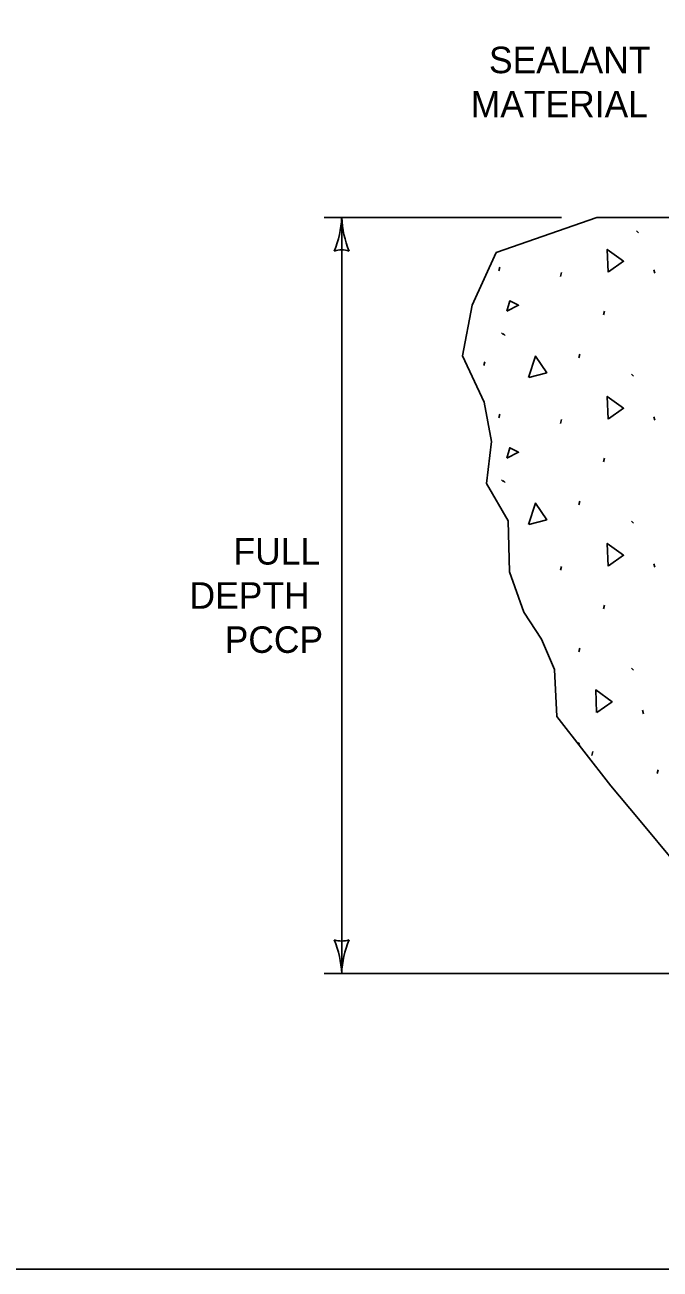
# Model space of a CAD drawing. Extents: x 49979.1 to 50021, y 49966.7 to 50011.4.
# Drawn here: x 50005.834 to 50007.273, y 49987.799 to 49990.616 of the extents above; entities that cross this region are included whole.
import ezdxf

# ---------------------------------------------------------------- set-up
doc = ezdxf.new("R2010")
doc.units = 0
for name, color, linetype in [('Level 1', 7, 'Continuous'), ('Level 12', 7, 'Continuous'), ('Level 13', 7, 'Continuous'), ('Level 2', 7, 'Continuous'), ('Level 3', 7, 'Continuous')]:
    doc.layers.add(name, color=color, linetype=linetype)

msp = doc.modelspace()

# ---------------------------------------------------------------- linework, layer by layer
at = {"layer": 'Level 1'}
for p, q in [((50007.1292, 49990.1802), (50006.9015, 49990.1012)), ((50007.1292, 49990.1802), (50007.7836, 49990.1802)), ((50006.9015, 49990.1012), (50006.8467, 49989.9816)), ((50006.8467, 49989.9816), (50006.8248, 49989.867)), ((50006.8248, 49989.867), (50006.8741, 49989.7623)), ((50006.8741, 49989.7623), (50006.8905, 49989.6726)), ((50006.8905, 49989.6726), (50006.8796, 49989.5779)), ((50006.8796, 49989.5779), (50006.9289, 49989.4932)), ((50006.9289, 49989.4932), (50006.9313, 49989.3775)), ((50006.9313, 49989.3775), (50006.9638, 49989.2866)), ((50006.9638, 49989.2866), (50007.0038, 49989.2252)), ((50007.0038, 49989.2252), (50007.0338, 49989.157)), ((50007.0338, 49989.157), (50007.0388, 49989.0501)), ((50007.0388, 49989.0501), (50007.1613, 49988.8932)), ((50007.1613, 49988.8932), (50007.2238, 49988.8182)), ((50007.2238, 49988.8182), (50007.3089, 49988.7159))]:
    msp.add_line(p, q, dxfattribs=at)
msp.add_lwpolyline([(49999.3835, 49998.9992), (50016.7501, 49998.9992), (50016.7501, 49987.7988), (49999.3835, 49987.7988)], close=True, dxfattribs=at)
at = {"layer": 'Level 12'}
for p, q in [((50006.8556, 49990.0007), (50006.8588, 49990.008)), ((50007.0868, 49988.9915), (50007.0901, 49988.9867))]:
    msp.add_line(p, q, dxfattribs=at)
at = {"layer": 'Level 13'}
for p, q in [((50007.2195, 49990.1503), (50007.2239, 49990.1457)), ((50006.9076, 49990.0593), (50006.9098, 49990.0678)), ((50007.2587, 49990.0616), (50007.261, 49990.0539)), ((50007.0469, 49990.0469), (50007.049, 49990.0554)), ((50007.1444, 49989.9595), (50007.1465, 49989.968)), ((50006.9135, 49989.9188), (50006.9179, 49989.9142)), ((50006.9173, 49989.9174), (50006.9218, 49989.9128)), ((50007.0885, 49989.8621), (50007.0906, 49989.8706)), ((50006.8733, 49989.8449), (50006.8754, 49989.8534)), ((50007.2077, 49989.8254), (50007.2121, 49989.8208)), ((50006.9076, 49989.7265), (50006.9098, 49989.735)), ((50007.0469, 49989.7141), (50007.049, 49989.7226)), ((50007.2587, 49989.7288), (50007.261, 49989.7211)), ((50007.1444, 49989.6267), (50007.1465, 49989.6352)), ((50006.9135, 49989.586), (50006.9179, 49989.5813)), ((50006.9173, 49989.5846), (50006.9218, 49989.58)), ((50007.0885, 49989.5293), (50007.0906, 49989.5377)), ((50007.2077, 49989.4926), (50007.2121, 49989.4879)), ((50007.0469, 49989.3813), (50007.049, 49989.3898)), ((50007.2587, 49989.396), (50007.261, 49989.3883)), ((50007.1444, 49989.2939), (50007.1465, 49989.3024)), ((50007.0885, 49989.1964), (50007.0906, 49989.2049)), ((50007.2077, 49989.1597), (50007.2121, 49989.1551)), ((50007.2325, 49989.0642), (50007.2347, 49989.0565)), ((50007.1181, 49988.9621), (50007.1202, 49988.9706)), ((50007.266, 49988.9213), (50007.2681, 49988.9298))]:
    msp.add_line(p, q, dxfattribs=at)
for points in [[(50007.1549, 49990.0566), (50007.153, 49990.1078), (50007.19, 49990.081), (50007.1557, 49990.0571)], [(50006.9256, 49989.9678), (50006.9322, 49989.9915), (50006.952, 49989.9815), (50006.9256, 49989.9678)], [(50006.9746, 49989.8177), (50006.9904, 49989.8664), (50007.016, 49989.8286), (50006.9755, 49989.8178)], [(50007.1549, 49989.7238), (50007.153, 49989.775), (50007.19, 49989.7482), (50007.1557, 49989.7243)], [(50006.9256, 49989.635), (50006.9322, 49989.6587), (50006.952, 49989.6487), (50006.9256, 49989.635)], [(50006.9746, 49989.4848), (50006.9904, 49989.5336), (50007.016, 49989.4957), (50006.9755, 49989.485)], [(50007.1549, 49989.391), (50007.153, 49989.4422), (50007.19, 49989.4154), (50007.1557, 49989.3914)], [(50007.1287, 49989.0592), (50007.1268, 49989.1104), (50007.1638, 49989.0836), (50007.1294, 49989.0596)]]:
    msp.add_lwpolyline(points, dxfattribs=at)
at = {"layer": 'Level 3'}
for p, q in [((50007.0492, 49990.1802), (50006.5116, 49990.1803)), ((50006.5516, 49988.4683), (50006.5516, 49990.1803)), ((50007.4513, 49988.4683), (50006.5116, 49988.4683))]:
    msp.add_line(p, q, dxfattribs=at)
for centre, radius, start, end in [((50006.3294, 49990.1894), 0.2223, 337.456, 357.6395), ((50006.7843, 49990.1918), 0.233, 182.8273, 202.0772), ((50006.5516, 49990.0521), 0.0548, 72.1388, 107.8612), ((50006.5516, 49988.5965), 0.0548, 252.1388, 287.8612), ((50006.3189, 49988.4568), 0.233, 2.8273, 22.0772), ((50006.7737, 49988.4591), 0.2223, 157.456, 177.6395)]:
    msp.add_arc(centre, radius, start, end, dxfattribs=at)

# ---------------------------------------------------------------- texts
at = {"layer": 'Level 2'}
for s, p in [('SEALANT', (50006.8851, 49990.507)), ('MATERIAL', (50006.8439, 49990.407))]:
    msp.add_text(s, height=0.06, dxfattribs=at).set_placement(p)
for s, p in [('FULL ', (50006.3065, 49989.3943)), ('DEPTH ', (50006.207, 49989.2943)), ('PCCP', (50006.2866, 49989.1943))]:
    msp.add_text(s, height=0.06, rotation=360, dxfattribs=at).set_placement(p)

doc.saveas('drawing.dxf')
